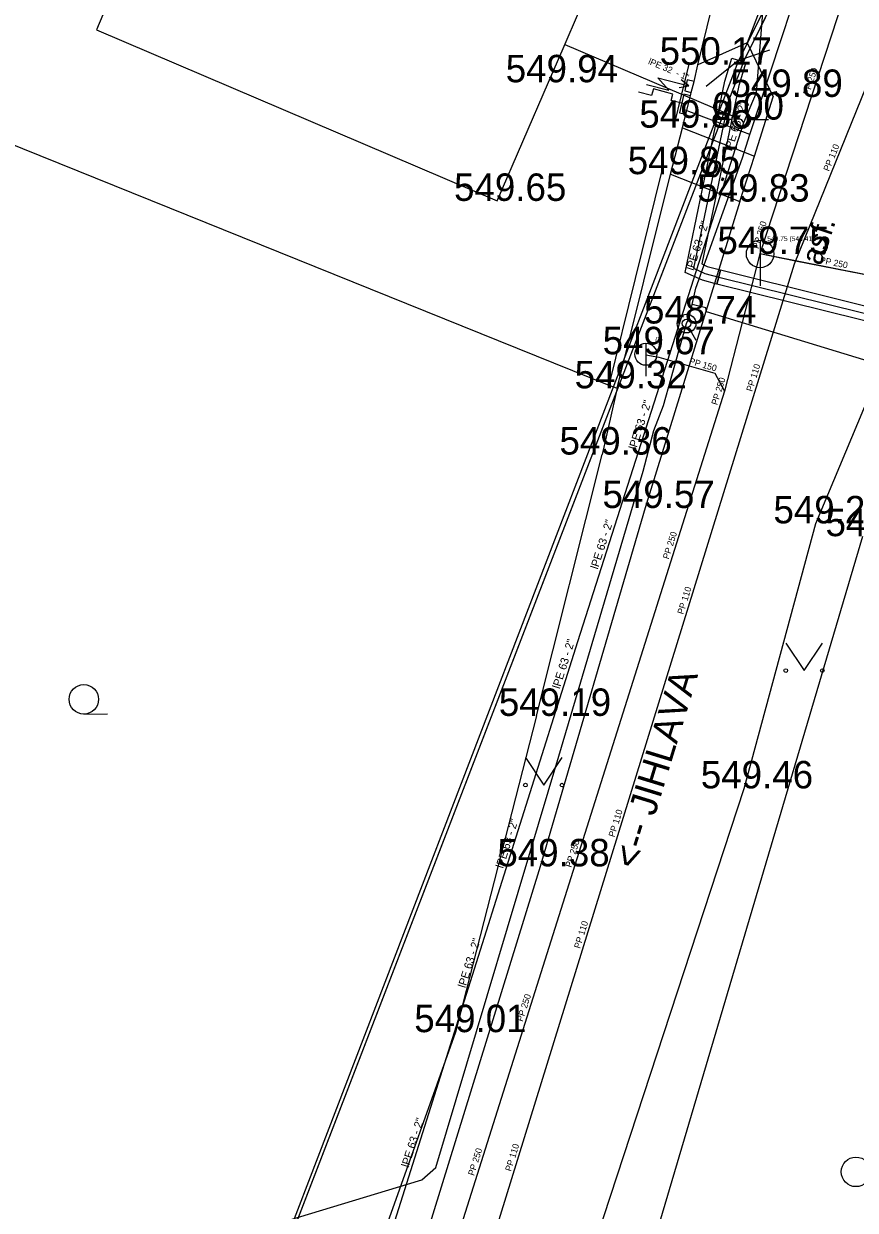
# Model space of a CAD drawing. Extents: x -669995 to -669686, y -1125551 to -1125263.
# Drawn here: x -669842.36 to -669819.65, y -1125358.09 to -1125325.67 of the extents above; entities that cross this region are included whole.
import ezdxf

# ---------------------------------------------------------------- set-up
doc = ezdxf.new("R2010")
doc.units = 0
for name, color, linetype in [('G_Bod_tecka', 7, 'Continuous'), ('G_Bod_vyska', 7, 'Continuous'), ('G_Budovy_Objekty', 7, 'Continuous'), ('G_Budovy_vstupy', 7, 'Continuous'), ('G_Cesty_Schody', 7, 'Continuous'), ('G_Plochy_zpevnene', 7, 'Continuous'), ('G_Ploty', 7, 'Continuous'), ('G_Ploty_vstupy', 7, 'Continuous'), ('G_Popisy_povrchu', 7, 'Continuous'), ('G_Poznamky_odkaz', 7, 'Continuous'), ('G_Site-kanalizace', 7, 'Continuous'), ('G_Site-plynovod', 7, 'Continuous'), ('G_Site-Rozvadece', 7, 'Continuous'), ('G_Site-vodovod', 7, 'Continuous'), ('G_Z_CHRANICKA-TEPLOVOD_kotovane', 7, 'Continuous'), ('G_Z_ELsilove_nadz_kotovane', 7, 'Continuous'), ('G_Z_ELsilove_podz_kotovane', 7, 'Continuous'), ('G_Z_KANAL_podz_kotovane', 7, 'Continuous'), ('G_Z_PLYNY_podz_geodeticky', 7, 'Continuous'), ('G_Z_VODA_podz_kotovane', 7, 'Continuous'), ('G_Zelen-Znacky', 7, 'Continuous'), ('Vrstva 1', 7, 'Continuous'), ('Vrstva 11', 7, 'Continuous'), ('Vrstva 2', 7, 'Continuous'), ('Vrstva 21', 7, 'Continuous'), ('Vrstva 26', 7, 'Continuous'), ('Vrstva 3', 7, 'Continuous'), ('Vrstva 4', 7, 'Continuous'), ('Vrstva 5', 7, 'Continuous'), ('Vrstva 6', 7, 'Continuous'), ('Vrstva 8', 7, 'Continuous')]:
    doc.layers.add(name, color=color, linetype=linetype)

msp = doc.modelspace()

# ---------------------------------------------------------------- linework, layer by layer
at = {"layer": 'G_Bod_tecka'}
for p, q in [((-669823.95, -1125326.79), (-669823.95, -1125326.79)), ((-669828.03, -1125327.27), (-669828.03, -1125327.27)), ((-669821.89, -1125327.67), (-669821.89, -1125327.67)), ((-669824.37, -1125328.51), (-669824.37, -1125328.51)), ((-669822.77, -1125328.29), (-669822.77, -1125328.29)), ((-669824.7, -1125329.78), (-669824.7, -1125329.78)), ((-669829.43, -1125330.51), (-669829.43, -1125330.51)), ((-669822.8, -1125330.53), (-669822.8, -1125330.53)), ((-669822.25, -1125331.96), (-669822.25, -1125331.96)), ((-669824.26, -1125333.86), (-669824.26, -1125333.86)), ((-669825.37, -1125334.7), (-669825.37, -1125334.7)), ((-669826.15, -1125335.63), (-669826.15, -1125335.63)), ((-669826.55, -1125337.44), (-669826.55, -1125337.44)), ((-669825.39, -1125338.9), (-669825.39, -1125338.9)), ((-669820.73, -1125339.32), (-669820.73, -1125339.32)), ((-669828.36, -1125344.58), (-669828.36, -1125344.58)), ((-669822.69, -1125346.56), (-669822.69, -1125346.56)), ((-669828.26, -1125348.69), (-669828.26, -1125348.69)), ((-669830.57, -1125353.22), (-669830.57, -1125353.22))]:
    msp.add_line(p, q, dxfattribs=at)
at = {"layer": 'G_Budovy_Objekty'}
for p, q in [((-669838.42, -1125321.24), (-669840.38, -1125325.84)), ((-669827.63, -1125326.35), (-669827.18, -1125325.31)), ((-669840.38, -1125325.84), (-669829.43, -1125330.51)), ((-669829.43, -1125330.51), (-669828.03, -1125327.27))]:
    msp.add_line(p, q, dxfattribs=at)
at = {"layer": 'G_Budovy_vstupy'}
msp.add_line((-669828.03, -1125327.27), (-669827.63, -1125326.35), dxfattribs=at)
at = {"layer": 'G_Cesty_Schody'}
msp.add_lwpolyline([(-669820.46, -1125320.59), (-669822.6, -1125326.19)], dxfattribs=at)
at = {"layer": 'G_Plochy_zpevnene'}
for p, q in [((-669822.6, -1125326.19), (-669821.89, -1125327.67)), ((-669822.8, -1125330.53), (-669825.39, -1125338.9)), ((-669820.73, -1125339.32), (-669818.64, -1125334.32)), ((-669825.39, -1125338.9), (-669828.26, -1125348.69)), ((-669822.69, -1125346.56), (-669820.73, -1125339.32)), ((-669827.51, -1125361.27), (-669822.69, -1125346.56)), ((-669828.26, -1125348.69), (-669831.59, -1125359.49))]:
    msp.add_line(p, q, dxfattribs=at)
for points in [[(-669822.6, -1125326.19), (-669823.95, -1125326.79)], [(-669822.4, -1125329.29), (-669821.89, -1125327.67)], [(-669824.37, -1125328.51), (-669822.4, -1125329.29)], [(-669822.8, -1125330.53), (-669822.4, -1125329.29)], [(-669824.7, -1125329.78), (-669822.8, -1125330.53)]]:
    msp.add_lwpolyline(points, dxfattribs=at)
at = {"layer": 'G_Ploty'}
for p, q in [((-669826.15, -1125335.63), (-669826.56, -1125337.44)), ((-669827.24, -1125366), (-669819.44, -1125339.67)), ((-669828.36, -1125344.58), (-669830.57, -1125353.22)), ((-669830.57, -1125353.22), (-669833.63, -1125361.78))]:
    msp.add_line(p, q, dxfattribs=at)
for points in [[(-669824.19, -1125326.74), (-669824.61, -1125328.45)], [(-669824.05, -1125327.25), (-669823.95, -1125326.79)], [(-669846.42, -1125327.46), (-669826.38, -1125335.54), (-669826.15, -1125335.63)], [(-669824.15, -1125327.64), (-669824.13, -1125327.55)], [(-669824.37, -1125328.51), (-669824.28, -1125328.14)], [(-669824.94, -1125329.72), (-669826.38, -1125335.54)], [(-669826.15, -1125335.63), (-669824.7, -1125329.78)]]:
    msp.add_lwpolyline(points, dxfattribs=at)
at = {"layer": 'G_Ploty_vstupy'}
msp.add_line((-669828.36, -1125344.58), (-669826.56, -1125337.44), dxfattribs=at)
for points in [[(-669823.95, -1125326.79), (-669822.44, -1125320.63)], [(-669824.7, -1125329.78), (-669824.37, -1125328.51)]]:
    msp.add_lwpolyline(points, dxfattribs=at)
at = {"layer": 'G_Site-kanalizace'}
for p, q in [((-669822.25, -1125331.585), (-669822.25, -1125332.835)), ((-669825.37, -1125334.4), (-669825.37, -1125335.3))]:
    msp.add_line(p, q, dxfattribs=at)
for centre, radius in [((-669822.25, -1125331.96), 0.375), ((-669825.37, -1125334.7), 0.3)]:
    msp.add_circle(centre, radius, dxfattribs=at)
at = {"layer": 'G_Site-plynovod'}
for p, q in [((-669824.51, -1125334.311), (-669824.384, -1125334.084)), ((-669824.136, -1125334.084), (-669824.01, -1125334.311))]:
    msp.add_line(p, q, dxfattribs=at)
for radius in [0.256, 0.118]:
    msp.add_circle((-669824.26, -1125333.86), radius, dxfattribs=at)
at = {"layer": 'G_Site-Rozvadece'}
for p, q in [((-669824.747, -1125327.487), (-669825.048, -1125327.152)), ((-669825.048, -1125327.152), (-669824.2, -1125327.37)), ((-669824.2, -1125327.37), (-669824.41, -1125327.202)), ((-669825.353, -1125327.332), (-669824.747, -1125327.487)), ((-669824.465, -1125327.415), (-669824.2, -1125327.37))]:
    msp.add_line(p, q, dxfattribs=at)
for points in [[(-669824.05, -1125327.25), (-669824.24, -1125327.2), (-669824.31, -1125327.5), (-669824.13, -1125327.55)], [(-669824.15, -1125327.64), (-669824.33, -1125327.59), (-669824.45, -1125328.1), (-669824.28, -1125328.14)]]:
    msp.add_lwpolyline(points, close=True, dxfattribs=at)
msp.add_lwpolyline([(-669824.32, -1125327.86), (-669824.676, -1125327.767), (-669824.63, -1125327.59), (-669825.165, -1125327.451), (-669825.212, -1125327.628), (-669825.568, -1125327.536)], dxfattribs=at)
at = {"layer": 'G_Site-vodovod'}
for p, q in [((-669823.02, -1125328.29), (-669823.52, -1125328.29)), ((-669822.52, -1125328.29), (-669822.02, -1125328.29))]:
    msp.add_line(p, q, dxfattribs=at)
msp.add_circle((-669822.77, -1125328.29), 0.25, dxfattribs=at)
at = {"layer": 'G_Z_CHRANICKA-TEPLOVOD_kotovane'}
for points in [[(-669823.431, -1125332.783), (-669823.827, -1125332.679), (-669824.299, -1125332.466), (-669823.212, -1125327.242), (-669823.021, -1125326.612), (-669822.641, -1125326.733), (-669822.828, -1125327.358), (-669823.842, -1125332.234), (-669823.693, -1125332.301), (-669823.332, -1125332.396), (-669823.329, -1125332.397), (-669823.379, -1125332.585)], [(-669823.332, -1125332.396), (-669823.329, -1125332.397), (-669817.412, -1125333.866), (-669817.46, -1125334.06), (-669817.508, -1125334.254), (-669817.513, -1125334.253), (-669823.428, -1125332.784), (-669823.379, -1125332.585)]]:
    msp.add_lwpolyline(points, close=True, dxfattribs=at)
at = {"layer": 'G_Z_ELsilove_nadz_kotovane'}
for points in [[(-669822.83, -1125326.67), (-669806.73, -1125294.49), (-669793.764, -1125277.296)], [(-669822.83, -1125326.67), (-669821.985, -1125326.386)], [(-669849.93, -1125407.07), (-669848.469, -1125402.12), (-669848.385, -1125401.833), (-669837.47, -1125364.84), (-669822.83, -1125326.67)], [(-669822.83, -1125326.67), (-669823.723, -1125327.386)]]:
    msp.add_lwpolyline(points, dxfattribs=at)
at = {"layer": 'G_Z_ELsilove_podz_kotovane'}
for points in [[(-669793.678, -1125277.309), (-669806.73, -1125294.49), (-669822.69, -1125326.67), (-669837.43, -1125364.93), (-669849.93, -1125407.07), (-669860.28, -1125448.68)], [(-669823.135, -1125327.854), (-669824.07, -1125332.35), (-669823.76, -1125332.49), (-669823.38, -1125332.59), (-669817.46, -1125334.06), (-669816.403, -1125334.349), (-669816.207, -1125334.402), (-669815.85, -1125334.5), (-669805.57, -1125337.27), (-669805.56, -1125338)]]:
    msp.add_lwpolyline(points, dxfattribs=at)
at = {"layer": 'G_Z_KANAL_podz_kotovane'}
msp.add_line((-669819.67, -1125324.06), (-669822.26, -1125331.96), dxfattribs=at)
for points in [[(-669837.47, -1125406.42), (-669844.1, -1125405.26), (-669833.36, -1125371.21), (-669821.31, -1125332.23), (-669811.44, -1125307.86), (-669795.39, -1125283.71), (-669791, -1125278.72), (-669790.199, -1125277.833)], [(-669822.26, -1125331.96), (-669823.22, -1125335.71), (-669834.34, -1125370.92)], [(-669818.39, -1125332.72), (-669821.28, -1125332.15), (-669822.26, -1125331.96)], [(-669825.37, -1125334.72), (-669825.02, -1125334.78), (-669823.49, -1125335.22), (-669823.22, -1125335.71)]]:
    msp.add_lwpolyline(points, dxfattribs=at)
at = {"layer": 'G_Z_PLYNY_podz_geodeticky'}
for points in [[(-669837.38, -1125359.92), (-669836.39, -1125358.74), (-669831.49, -1125357.25), (-669831.11, -1125356.92), (-669827.75, -1125345.68), (-669825.44, -1125337.89), (-669825.15, -1125336.78), (-669824.89, -1125336.1), (-669824.26, -1125333.86), (-669824.2, -1125333.72), (-669824.11, -1125333.34), (-669824.01, -1125332.89), (-669822.73, -1125329.33), (-669822.53, -1125328.7), (-669820.54, -1125322.64), (-669816.69, -1125313.26), (-669812.22, -1125303.65), (-669812, -1125303.3), (-669811.72, -1125302.91), (-669809.57, -1125300.17), (-669804.79, -1125292.58), (-669800.14, -1125285.7), (-669795.88, -1125280.51), (-669793.302, -1125277.366)], [(-669822.53, -1125328.7), (-669822.72, -1125328.62), (-669824.2, -1125328.07), (-669824.33, -1125328.01)], [(-669817.9, -1125335.32), (-669818.55, -1125335.12), (-669823.71, -1125333.54), (-669823.73, -1125333.43), (-669824.11, -1125333.34)]]:
    msp.add_lwpolyline(points, dxfattribs=at)
at = {"layer": 'G_Z_VODA_podz_kotovane'}
for points in [[(-669793.904, -1125277.275), (-669806.05, -1125295.04), (-669809.12, -1125297.97), (-669810.25, -1125299.77), (-669811.13, -1125301.2), (-669814.74, -1125307.05), (-669820.1, -1125318), (-669821.98, -1125322.82), (-669822.36, -1125327.56), (-669822.7, -1125328.38), (-669827.24, -1125342.56), (-669833.54, -1125362.52), (-669834.09, -1125363.24)], [(-669827.58, -1125326.24), (-669822.77, -1125328.29), (-669822.7, -1125328.38)]]:
    msp.add_lwpolyline(points, dxfattribs=at)
at = {"layer": 'G_Zelen-Znacky'}
for p, q in [((-669821.55, -1125342.59), (-669821.05, -1125343.34)), ((-669821.05, -1125343.34), (-669820.55, -1125342.59)), ((-669840.722, -1125344.53), (-669840.072, -1125344.527)), ((-669828.66, -1125345.72), (-669828.16, -1125346.47)), ((-669828.16, -1125346.47), (-669827.66, -1125345.72))]:
    msp.add_line(p, q, dxfattribs=at)
for centre, radius in [((-669821.55, -1125343.34), 0.05), ((-669820.55, -1125343.34), 0.05), ((-669840.722, -1125344.127), 0.403), ((-669828.66, -1125346.47), 0.05), ((-669827.66, -1125346.47), 0.05), ((-669819.632, -1125357.037), 0.403)]:
    msp.add_circle(centre, radius, dxfattribs=at)
at = {"layer": 'Vrstva 1'}
msp.add_line((-669822.69, -1125326.67), (-669822.69, -1125326.67), dxfattribs=at)
at = {"layer": 'Vrstva 11'}
msp.add_line((-669819.67, -1125324.06), (-669822.26, -1125331.96), dxfattribs=at)
for points in [[(-669822.26, -1125331.96), (-669823.22, -1125335.71), (-669834.34, -1125370.92)], [(-669818.39, -1125332.72), (-669821.279, -1125332.153), (-669822.26, -1125331.96)], [(-669825.37, -1125334.72), (-669825.02, -1125334.78), (-669823.49, -1125335.22), (-669823.22, -1125335.71)]]:
    msp.add_lwpolyline(points, dxfattribs=at)
at = {"layer": 'Vrstva 21'}
msp.add_lwpolyline([(-669837.47, -1125406.42), (-669844.1, -1125405.26), (-669833.36, -1125371.21), (-669821.31, -1125332.23), (-669811.44, -1125307.86), (-669795.39, -1125283.71), (-669791, -1125278.72), (-669790.199, -1125277.833)], dxfattribs=at)
at = {"layer": 'Vrstva 26'}
for points in [[(-669793.906, -1125277.275), (-669806.05, -1125295.04), (-669809.12, -1125297.97), (-669810.25, -1125299.77), (-669811.134, -1125301.203), (-669814.74, -1125307.05), (-669820.1, -1125318), (-669821.98, -1125322.82), (-669822.36, -1125327.56), (-669822.7, -1125328.38), (-669827.24, -1125342.56), (-669833.535, -1125362.519), (-669834.09, -1125363.24)], [(-669827.583, -1125326.239), (-669822.77, -1125328.29), (-669822.7, -1125328.38)]]:
    msp.add_lwpolyline(points, dxfattribs=at)
at = {"layer": 'Vrstva 5'}
for p, q in [((-669806.73, -1125294.49), (-669822.69, -1125326.67)), ((-669822.69, -1125326.67), (-669837.43, -1125364.93))]:
    msp.add_line(p, q, dxfattribs=at)
at = {"layer": 'Vrstva 6'}
msp.add_line((-669822.77, -1125328.29), (-669822.77, -1125328.29), dxfattribs=at)
at = {"layer": 'Vrstva 8'}
for p, q in [((-669822.26, -1125331.96), (-669822.26, -1125331.96)), ((-669825.37, -1125334.72), (-669825.37, -1125334.72))]:
    msp.add_line(p, q, dxfattribs=at)

# ---------------------------------------------------------------- texts
at = {"layer": 'G_Bod_vyska'}
for s, p in [('550.17', (-669824.994, -1125326.79)), ('549.94', (-669829.198, -1125327.27)), ('549.89', (-669823.058, -1125327.67)), ('0.00', (-669823.55, -1125328.29)), ('549.86', (-669825.55, -1125328.51)), ('549.85', (-669825.866, -1125329.78)), ('549.65', (-669830.61, -1125330.51)), ('549.83', (-669823.966, -1125330.53)), ('549.75', (-669823.416, -1125331.96)), ('548.74', (-669825.421, -1125333.86)), ('549.67', (-669826.55, -1125334.7)), ('549.32', (-669827.316, -1125335.63)), ('549.36', (-669827.73, -1125337.44)), ('549.57', (-669826.556, -1125338.9)), ('549.22', (-669821.886, -1125339.32)), ('549.12', (-669820.464, -1125339.67)), ('549.19', (-669829.386, -1125344.58)), ('549.46', (-669823.87, -1125346.56)), ('549.38', (-669829.426, -1125348.69)), ('549.01', (-669831.696, -1125353.22))]:
    msp.add_text(s, height=0.75, dxfattribs=at).set_placement(p)
at = {"layer": 'G_Popisy_povrchu'}
for s, rotation, p in [('b.', 338.459, (-669823.811, -1125329.758)), ('asf.', 71.7182, (-669820.584, -1125332.3))]:
    msp.add_text(s, height=0.6, rotation=rotation, dxfattribs=at).set_placement(p)
at = {"layer": 'G_Poznamky_odkaz'}
msp.add_text('<-- JIHLAVA', height=0.75, rotation=72.9895, dxfattribs=at).set_placement((-669825.579, -1125348.808))
at = {"layer": 'Vrstva 2'}
for s, height, p in [('549.75 (548.41)', 0.13163, (-669822.054, -1125331.607)), ('\xa0()', 0.1316, (-669825.165, -1125334.367))]:
    msp.add_text(s, height=height, dxfattribs=at).set_placement(p)
at = {"layer": 'Vrstva 3'}
for s, rotation, p in [('PP 250', 71.8255, (-669820.916, -1125327.636)), ('PP 110', 67.9311, (-669820.368, -1125329.716)), ('PP 250', 72.9064, (-669822.294, -1125331.832)), ('PP 250', 348.892, (-669820.63, -1125332.208)), ('PP 150', 343.9754, (-669824.203, -1125334.961)), ('PP 110', 72.9064, (-669822.466, -1125335.732)), ('PP 250', 72.8033, (-669823.42, -1125336.101)), ('PP 250', 72.4765, (-669824.747, -1125340.312)), ('PP 110', 72.8155, (-669824.348, -1125341.818)), ('PP 110', 72.867, (-669826.229, -1125347.905)), ('PP 250', 72.4641, (-669827.408, -1125348.733)), ('PP 110', 72.8033, (-669827.17, -1125350.948)), ('PP 250', 72.4517, (-669828.736, -1125352.945)), ('PP 250', 72.491, (-669830.066, -1125357.155)), ('PP 110', 72.8942, (-669829.052, -1125357.036))]:
    msp.add_text(s, height=0.1755, rotation=rotation, dxfattribs=at).set_placement(p)
at = {"layer": 'Vrstva 4'}
for s, height, rotation, p in [('lPE 32  - 1"', 0.17551, 336.8735, (-669825.322, -1125326.764)), ('lPE 63 - 2"', 0.21938, 72.1979, (-669823.025, -1125329.162)), ('lPE 63 - 2"', 0.21938, 72.2111, (-669824.07, -1125332.427)), ('lPE 63 - 2"', 0.21938, 72.2111, (-669825.638, -1125337.324)), ('lPE 63 - 2"', 0.21938, 72.2586, (-669826.683, -1125340.589)), ('lPE 63 - 2"', 0.21938, 72.51, (-669827.723, -1125343.855)), ('lPE 63 - 2"', 0.21938, 72.5305, (-669829.269, -1125348.759)), ('lPE 63 - 2"', 0.21938, 72.51, (-669830.301, -1125352.027)), ('lPE 63 - 2"', 0.21938, 72.51, (-669831.847, -1125356.931))]:
    msp.add_text(s, height=height, rotation=rotation, dxfattribs=at).set_placement(p)

doc.saveas('drawing.dxf')
